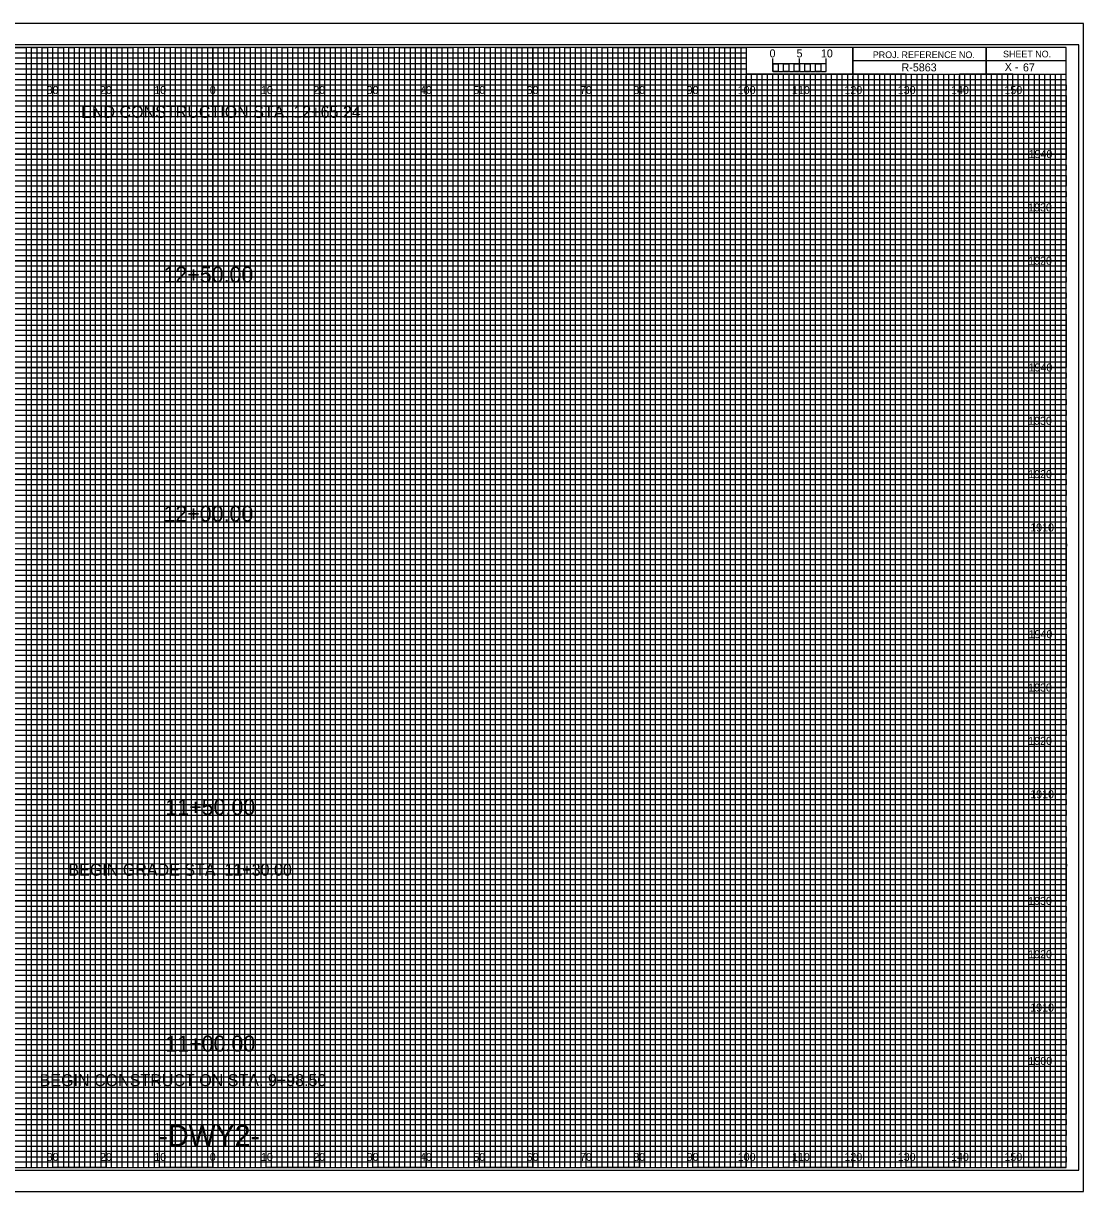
# Model space of a CAD drawing. Extents: x -13 to 323, y -4 to 214.
# Drawn here: x 124.5 to 323.3, y -4.5 to 214.5 of the extents above; entities that cross this region are included whole.
import ezdxf

# ---------------------------------------------------------------- set-up
doc = ezdxf.new("R2010")
doc.units = 0
for name, color, linetype in [('Prop XS Alignment Label', 7, 'Continuous'), ('Prop XS Bar Scale Labels', 7, 'Continuous'), ('Prop XS Elevation Labels', 7, 'Continuous'), ('Prop XS Offset Labels', 7, 'Continuous'), ('Prop XS Project Number', 7, 'Continuous'), ('Prop XS SE Text', 7, 'Continuous'), ('Prop XS Sheet Number', 7, 'Continuous'), ('Prop XS Station Labels', 7, 'Continuous'), ('Sheet Cross Section CELL', 7, 'Continuous'), ('Sheet Cross Section Grid Major CELL', 7, 'Continuous'), ('Sheet Cross Section Grid Middle CELL', 7, 'Continuous'), ('Sheet Cross Section Grid Minor 1 CELL', 7, 'Continuous'), ('Sheet Cross Section Grid Minor 2 CELL', 7, 'Continuous'), ('Sheet Cross Section Scale CELL', 7, 'Continuous'), ('Sheet Cutting Line CELL', 7, 'Continuous'), ('Sheet DOT Grid CELL', 7, 'Continuous'), ('Sheet Plot Border Inside CELL', 7, 'Continuous'), ('Sheet Plot Border Outside CELL', 7, 'Continuous')]:
    doc.layers.add(name, color=color, linetype=linetype)

msp = doc.modelspace()

# ---------------------------------------------------------------- linework, layer by layer
at = {"layer": 'Sheet Cross Section CELL'}
for p, q in [((305, 210), (305, 205)), ((305, 205), (305, 210)), ((280, 207.5), (280, 205)), ((320, 207.49), (280, 207.49)), ((280, 205), (320, 205))]:
    msp.add_line(p, q, dxfattribs=at)
for points in [[(320, 210), (0, 210), (0, 0), (320, 0)], [(280, 210), (260, 210), (260, 205.03), (280, 205.03)], [(320, 210), (280, 210), (280, 205), (320, 205)]]:
    msp.add_lwpolyline(points, close=True, dxfattribs=at)
at = {"layer": 'Sheet Cross Section Grid Major CELL'}
for p, q in [((130, 210), (120, 210)), ((130, 0), (130, 210)), ((150, 210), (140, 210)), ((140, 210), (140, 0)), ((150, 0), (150, 210)), ((170, 210), (160, 210)), ((160, 210), (160, 0)), ((170, 0), (170, 210)), ((190, 210), (180, 210)), ((180, 210), (180, 0)), ((190, 0), (190, 210)), ((210, 210), (200, 210)), ((200, 210), (200, 0)), ((210, 0), (210, 210)), ((230, 210), (220, 210)), ((220, 210), (220, 0)), ((230, 0), (230, 210)), ((250, 210), (240, 210)), ((240, 210), (240, 0)), ((250, 0), (250, 210)), ((260, 210), (260, 0)), ((270, 0), (270, 205)), ((290, 205), (280, 205)), ((280, 205), (280, 0)), ((290, 0), (290, 205)), ((310, 205), (300, 205)), ((300, 205), (300, 0)), ((310, 0), (310, 205)), ((140, 0), (130, 0)), ((160, 0), (150, 0)), ((180, 0), (170, 0)), ((200, 0), (190, 0)), ((220, 0), (210, 0)), ((240, 0), (230, 0)), ((260, 0), (250, 0)), ((280, 0), (270, 0)), ((300, 0), (290, 0)), ((320, 0), (310, 0)), ((320, 0), (320, 0))]:
    msp.add_line(p, q, dxfattribs=at)
for points in [[(0, 200), (320, 200), (320, 190), (0, 190)], [(0, 180), (320, 180), (320, 170), (0, 170)], [(0, 160), (320, 160), (320, 150), (0, 150)], [(0, 140), (320, 140), (320, 130), (0, 130)], [(0, 120), (320, 120), (320, 110), (0, 110)], [(0, 100), (320, 100), (320, 90), (0, 90)], [(0, 80), (320, 80), (320, 70), (0, 70)], [(0, 60), (320, 60), (320, 50), (0, 50)], [(0, 40), (320, 40), (320, 30), (0, 30)], [(0, 20), (320, 20), (320, 10), (0, 10)]]:
    msp.add_lwpolyline(points, dxfattribs=at)
at = {"layer": 'Sheet Cross Section Grid Middle CELL'}
for points in [[(115, 210), (125, 210), (125, 0), (135, 0), (135, 210), (145, 210), (145, 0), (155, 0), (155, 210), (165, 210), (165, 0), (175, 0), (175, 210), (185, 210), (185, 0), (195, 0), (195, 210), (205, 210), (205, 0), (215, 0), (215, 210), (225, 210), (225, 0), (235, 0), (235, 210), (245, 210), (245, 0), (255, 0), (255, 210), (259.93, 210), (260, 210), (260, 205), (264.99, 205), (264.99, 0), (275, 0), (275, 205), (285, 205), (285, 0), (295, 0), (295, 205), (305, 205), (305, 0), (315, 0), (315, 205)], [(0, 205), (275, 205)], [(0, 185), (320, 185), (320, 195), (0, 195)], [(0, 165), (320, 165), (320, 175), (0, 175)], [(0, 145), (320, 145), (320, 155), (0, 155)], [(0, 125), (320, 125), (320, 135), (0, 135)], [(0, 105), (320, 105), (320, 115), (0, 115)], [(0, 85), (320, 85), (320, 95), (0, 95)], [(0, 65), (320, 65), (320, 75), (0, 75)], [(0, 45), (320, 45), (320, 55), (0, 55)], [(0, 25), (320, 25), (320, 35), (0, 35)], [(0, 5), (320, 5), (320, 15), (0, 15)]]:
    msp.add_lwpolyline(points, dxfattribs=at)
at = {"layer": 'Sheet Cross Section Grid Minor 1 CELL'}
for p, q in [((0, 209), (260, 209)), ((260, 209), (260, 207.98)), ((260, 207.98), (0, 207.98)), ((0, 207), (260, 207)), ((260, 205.89), (0, 205.89)), ((260, 207), (260, 205.89)), ((0, 204), (320, 204))]:
    msp.add_line(p, q, dxfattribs=at)
for points in [[(0, 203), (270, 203), (320, 203), (320, 202), (0, 202)], [(0, 201), (320, 201), (320, 199), (0, 199)], [(0, 198), (320, 198), (320, 197), (0, 196.98)], [(0, 196), (320, 196), (320, 194), (0, 194)], [(0, 193), (320, 193), (320, 192), (0, 192)], [(0, 191), (320, 191), (320, 189), (0, 189)], [(0, 188), (320, 188), (320, 187), (0, 187)], [(0, 186), (320, 186), (320, 184), (0, 184)], [(0, 183), (320, 183), (320, 182), (0, 182)], [(0, 181), (320, 181), (320, 179), (0, 179)], [(0, 178), (320, 178), (320, 177), (0, 177)], [(0, 176), (320, 176), (320, 173.95), (320, 173), (320, 172), (0, 172)], [(0, 174), (320, 174), (320, 173), (0, 173)], [(0, 171), (320, 171), (320, 169), (0, 169.03)], [(0, 169.03), (320, 169), (320, 168), (0, 168)], [(0, 167), (320, 167), (320, 166), (0, 166)], [(0, 164), (320, 164), (320, 163), (0, 163)], [(0, 162), (320, 162), (320, 161), (0, 161)], [(-0.07, 158.89), (320, 158.89), (320, 157.88), (-0.07, 157.88)], [(0, 157), (320, 157), (320, 156), (0, 156)], [(0, 154), (320, 154), (320, 153), (0, 153)], [(0, 152), (320, 152), (320, 151), (0, 151)], [(0, 149), (320, 149), (320, 148), (0, 148)], [(0, 147), (320, 147), (320, 146), (0, 146)], [(0, 144), (320, 144), (320, 143), (0, 143)], [(0, 142), (320, 142), (320, 141), (0, 141)], [(0, 139), (320, 139), (319.99, 137.98), (0, 138)], [(0, 137), (320, 137), (320, 136), (0, 136)], [(0, 134), (320, 134), (320, 133), (0, 133)], [(0, 132), (320, 132), (320, 131), (0, 131)], [(0, 129), (320, 129), (320, 128), (0, 128)], [(0, 127), (320, 127), (320, 126), (0, 126)], [(0, 124), (320, 124), (320, 123), (0, 123)], [(0, 122), (320, 122), (320, 121), (0, 121)], [(0, 119), (320, 119), (320, 118), (0, 118)], [(0, 116.99), (320.07, 116.91), (320, 116), (0, 116)], [(0, 114), (320, 114), (320, 113), (0, 113)], [(0, 112), (320, 112), (320, 111), (0, 111)], [(0, 109), (320, 109), (320, 108), (0, 108)], [(0, 107), (320, 107), (320, 106), (0, 106)], [(0, 104), (320, 104), (320, 103), (0, 103)], [(0, 102), (320, 102), (320, 101), (0, 101)], [(0, 99), (320, 99), (320, 98), (0, 98)], [(0, 97), (320, 97), (320, 96), (0, 96)], [(0, 94), (320, 94), (320, 93), (0, 93)], [(0, 92), (320, 92), (320, 91), (0, 91)], [(0, 89), (320, 89), (320, 88), (0, 88)], [(0, 87), (320, 87), (320, 86), (0, 86)], [(0, 84), (320, 84), (320, 83), (0, 83)], [(0, 82), (320, 82), (320, 81), (0, 81)], [(0, 79), (320, 79), (319.99, 77.98), (0, 78)], [(0, 77), (320, 77), (320, 76), (0, 76)], [(0, 74), (320, 74), (320, 73), (0, 73)], [(0, 72), (320, 72), (320, 71), (0, 71)], [(0, 69), (320, 69), (320, 68), (0, 68)], [(0, 67), (320, 67), (320, 66), (0, 66)], [(0, 64), (320, 64), (320, 63), (0, 63)], [(0, 62), (320, 62), (320, 61), (0, 61)], [(0, 59), (320, 59), (320, 58), (0, 58)], [(0, 56.99), (320.07, 56.91), (320, 56), (0, 56)], [(0, 54), (320, 54), (320, 53), (0, 53)], [(0, 52), (320, 52), (320, 51), (0, 51)], [(0, 49), (320, 49), (320, 48), (0, 48)], [(0, 47), (320, 47), (320, 46), (0, 46)], [(0, 44), (320, 44), (320, 43), (0, 43)], [(0, 42), (320, 42), (320, 41), (0, 41)], [(0, 39), (320, 39), (320, 38), (0, 38)], [(0, 37), (320, 37), (320, 36), (0, 36)], [(0, 34), (320, 34), (320, 33), (0, 33)], [(0, 32), (320, 32), (320, 31), (0, 31)], [(0, 29), (320, 29), (320, 28), (0, 28)], [(0, 27), (320, 27), (320, 26), (0, 26)], [(0, 24), (320, 24), (320, 23), (0, 23)], [(0, 22), (320, 22), (320, 21), (0, 21)], [(0, 19), (320, 19), (320, 18), (0, 18)], [(0, 17), (320, 17), (320, 16), (0, 16)], [(0, 14), (320, 14), (320, 13), (0, 13)], [(0, 12), (320, 12), (320, 11), (0, 11)], [(0, 9), (320, 9), (320, 8), (0, 8)], [(0, 7), (320, 7), (320, 6), (0, 6)], [(0, 4), (320, 4), (320, 3), (0, 3)], [(0, 2), (320, 2), (320, 1), (0, 1)]]:
    msp.add_lwpolyline(points, dxfattribs=at)
at = {"layer": 'Sheet Cross Section Grid Minor 2 CELL'}
for p, q in [((267, 205), (266.01, 205)), ((266.01, 205), (266.01, 0)), ((267, 0), (267, 205)), ((269, 205), (268, 205)), ((268, 205), (268, 0)), ((269, 0), (269, 205)), ((266.01, 0), (265, 0)), ((268, 0), (267, 0))]:
    msp.add_line(p, q, dxfattribs=at)
for points in [[(125, 0), (126, 0), (126, 210), (127, 210), (127, 0)], [(127, 0), (128, 0), (128, 210), (129, 210), (129, 0)], [(130, 0), (131, 0), (131, 210), (132, 210), (132, 0)], [(132, 0), (133, 0), (133, 210), (134, 210), (134, 0)], [(135, 0), (136, 0), (136, 210), (137, 210), (137, 0)], [(137, 0), (138, 0), (138, 210), (139, 210), (139, 0)], [(140, 0), (141, 0), (141, 210), (142, 210), (142, 0)], [(142, 0), (143, 0), (143, 210), (144, 210), (144, 0)], [(145, 0), (146, 0), (146, 210), (147, 210), (147, 0)], [(147, 0), (148, 0), (148, 210), (149, 210), (149, 0)], [(150, 0), (151, 0), (151, 210), (152, 210), (152, 0)], [(152, 0), (153, 0), (153, 210), (154, 210), (154, 0)], [(155, 0), (156, 0), (156, 210), (157, 210), (157, 0)], [(157, 0), (158, 0), (158, 210), (159, 210), (159, 0)], [(160, 0), (161, 0), (161, 210), (162, 210), (162, 0)], [(162, 0), (163, 0), (163, 210), (164, 210), (164, 0)], [(165, 0), (166, 0), (166, 210), (167, 210), (167, 0)], [(167, 0), (168, 0), (168, 210), (169, 210), (169, 0)], [(170, 0), (171, 0), (171, 210), (172, 210), (172, 0)], [(172, 0), (173, 0), (173, 210), (174, 210), (174, 0)], [(175, 0), (176, 0), (176, 210), (177, 210), (177, 0)], [(177, 0), (178, 0), (178, 210), (179, 210), (179, 0)], [(180, 0), (181, 0), (181, 210), (182, 210), (182, 0)], [(182, 0), (183, 0), (183, 210), (184, 210), (184, 0)], [(185, 0), (186, 0), (186, 210), (187, 210), (187, 0)], [(187, 0), (188, 0), (188, 210), (189, 210), (189, 0)], [(190, 0), (191, 0), (191, 210), (192, 210), (192, 0)], [(192, 0), (193, 0), (193, 210), (194, 210), (194, 0)], [(195, 0), (196, 0), (196, 210), (197, 210), (197, 0)], [(197, 0), (198, 0), (198, 210), (199, 210), (199, 0)], [(200, 0), (201, 0), (201, 210), (202, 210), (202, 0)], [(202, 0), (203, 0), (203, 210), (204, 210), (204, 0)], [(205, 0), (206, 0), (206, 210), (207, 210), (207, 0)], [(207, 0), (208, 0), (208, 210), (209, 210), (209, 0)], [(210, 0), (211, 0), (211, 210), (212, 210), (212, 0)], [(212, 0), (213, 0), (213, 210), (214, 210), (214, 0)], [(215, 0), (216, 0), (216, 210), (217, 210), (217, 0)], [(217, 0), (218, 0), (218, 210), (219, 210), (219, 0)], [(220, 0), (221, 0), (221, 210), (222, 210), (222, 0)], [(222, 0), (223, 0), (223, 210), (224, 210), (224, 0)], [(225, 0), (226, 0), (226, 210), (227, 210), (227, 0)], [(227, 0), (228, 0), (228, 210), (229, 210), (229, 0)], [(230, 0), (231, 0), (231, 210), (232, 210), (232, 0)], [(232, 0), (233, 0), (233, 210), (234, 210), (234, 0)], [(235, 0), (236, 0), (236, 210), (237, 210), (237, 0)], [(237, 0), (238, 0), (238, 210), (239, 210), (239, 0)], [(240, 0), (241, 0), (241, 210), (242, 210), (242, 0)], [(242, 0), (243, 0), (243, 210), (244, 210), (244, 0)], [(245, 0), (246, 0), (246, 210), (247, 210), (247, 0)], [(247, 0), (248, 0), (248, 210), (249, 210), (249, 0)], [(250, 0), (251, 0), (251, 210), (252, 210), (252, 0)], [(252, 0), (253, 0), (253, 210), (254, 210), (254, 0)], [(255, 0), (256, 0), (256, 210), (257, 210), (257, 0)], [(257, 0), (258, 0), (258, 210), (259, 210), (259, 0)], [(260, 0), (261, 0), (261, 205), (262.02, 205), (262.02, 0)], [(262, 0), (263, 0), (263, 205), (263.99, 205), (263.99, 0)], [(270, 0), (270.98, 0), (270.98, 205), (272, 205), (272, 0)], [(272, 0), (273, 0), (273, 205), (274.05, 205), (274.05, 0)], [(275, 0), (276, 0), (276, 205), (277, 205), (277, 0)], [(277, 0), (278, 0), (278, 205), (279, 205), (279, 0)], [(280, 0), (281, 0), (281, 205), (282, 205), (282, 0)], [(282, 0), (283, 0), (283, 205), (284, 205), (284, 0)], [(285, 0), (286, 0), (286, 205), (287, 205), (287, 0)], [(287, 0), (288, 0), (288, 205), (289, 205), (289, 0)], [(290, 0), (291, 0), (291, 205), (292, 205), (292, 0)], [(292, 0), (293, 0), (293, 205), (294, 205), (294, 0)], [(295, 0), (296, 0), (296, 205), (297, 205), (297, 0)], [(297, 0), (298, 0), (298, 205), (299, 205), (299, 0)], [(300, 0), (301, 0), (301, 205), (302, 205), (302, 0)], [(302, 0), (303, 0), (303, 205), (304, 205), (304, 0)], [(305, 0), (306, 0), (306, 205), (307, 205), (307, 0)], [(307, 0), (308, 0), (308, 205), (309, 205), (309, 0)], [(310, 0), (311, 0), (311, 205), (312, 205), (312, 0)], [(312, 0), (313, 0), (313, 205), (314, 205), (314, 0)], [(315, 0), (316, 0), (316, 205), (317, 205), (317, 0)], [(317, 0), (318, 0), (318, 205), (319, 205), (319, 0)]]:
    msp.add_lwpolyline(points, dxfattribs=at)
at = {"layer": 'Sheet Cross Section Scale CELL'}
for p, q in [((265, 205.49), (265, 207.9)), ((265, 206.9), (265, 207.9)), ((270, 205.49), (270, 207.9)), ((275, 205.49), (275, 207.9)), ((275, 206.9), (275, 207.9))]:
    msp.add_line(p, q, dxfattribs=at)
for points in [[(275, 206.9), (265, 206.9), (265, 205.49), (275, 205.49)], [(265, 206.9), (266, 206.9), (266, 205.49), (265, 205.49)], [(267, 206.9), (268, 206.9), (268, 205.49), (267, 205.49)], [(269, 206.9), (270, 206.9), (270, 205.49), (269, 205.49)], [(271, 206.9), (272, 206.9), (272, 205.49), (271, 205.49)], [(273, 206.9), (274, 206.9), (274, 205.49), (273, 205.49)]]:
    msp.add_lwpolyline(points, close=True, dxfattribs=at)
at = {"layer": 'Sheet Cutting Line CELL'}
for p, q in [((323.3, 214.5), (-13.4, 214.5)), ((-13.4, -4.5), (323.3, -4.5))]:
    msp.add_line(p, q, dxfattribs=at)
at = {"layer": 'Sheet DOT Grid CELL'}
for p, q in [((130, 0), (130, 210)), ((140, 0), (140, 210)), ((150, 0), (150, 210)), ((160, 0), (160, 210)), ((170, 0), (170, 210)), ((180, 0), (180, 210)), ((190, 0), (190, 210)), ((200, 0), (200, 210)), ((210, 0), (210, 210)), ((220, 0), (220, 210)), ((230, 0), (230, 210)), ((240, 0), (240, 210)), ((250, 0), (250, 210)), ((260, 0), (260, 204.69)), ((270, 0), (270, 204.69)), ((280, 0), (280, 204.69)), ((290, 0), (290, 204.69)), ((300, 0), (300, 204.69)), ((310, 0), (310, 204.69)), ((0, 200), (320, 200)), ((0, 190), (320, 190)), ((0, 180), (320, 180)), ((0, 170), (320, 170)), ((0, 160), (320, 160)), ((0, 150), (320, 150)), ((0, 140), (320, 140)), ((0, 130), (320, 130)), ((0, 120), (320, 120)), ((0, 110), (320, 110)), ((0, 100), (320, 100)), ((0, 90), (320, 90)), ((0, 80), (320, 80)), ((0, 70), (320, 70)), ((0, 60), (320, 60)), ((0, 50), (320, 50)), ((0, 40), (320, 40)), ((0, 30), (320, 30)), ((0, 20), (320, 20)), ((0, 10), (320, 10))]:
    msp.add_line(p, q, dxfattribs=at)
at = {"layer": 'Sheet Plot Border Inside CELL'}
msp.add_lwpolyline([(-10.8, -0.5), (322.4, -0.5), (322.4, 210.5), (-10.8, 210.5)], close=True, dxfattribs=at)
at = {"layer": 'Sheet Plot Border Outside CELL'}
msp.add_lwpolyline([(-13.4, -4.5), (323.3, -4.5), (323.3, 214.5), (-13.4, 214.5)], close=True, dxfattribs=at)

# ---------------------------------------------------------------- texts
at = {"layer": 'Prop XS Alignment Label'}
msp.add_text('-DWY2-', height=4, dxfattribs=at).set_placement((149.85, 4))
at = {"layer": 'Prop XS Bar Scale Labels'}
for s, p in [('5', (269.47, 208.12)), ('10', (274.04, 208.12))]:
    msp.add_text(s, height=1.5, dxfattribs=at).set_placement(p)
at = {"layer": 'Prop XS Elevation Labels'}
for s, p in [('1940', (312.97, 189.25)), ('1930', (312.89, 179.25)), ('1920', (312.9, 169.25)), ('1940', (312.97, 149.25)), ('1930', (312.89, 139.25)), ('1920', (312.9, 129.25)), ('1910', (313.28, 119.25)), ('1940', (312.97, 99.25)), ('1930', (312.89, 89.25)), ('1920', (312.9, 79.25)), ('1910', (313.28, 69.25)), ('1930', (312.89, 49.25)), ('1920', (312.9, 39.25)), ('1910', (313.28, 29.25)), ('1900', (312.95, 19.25))]:
    msp.add_text(s, height=1.5, dxfattribs=at).set_placement(p)
at = {"layer": 'Prop XS Offset Labels'}
for s, p in [('30', (128.86, 201.25)), ('20', (138.86, 201.25)), ('10', (149.04, 201.25)), ('0', (159.45, 201.25)), ('0', (159.45, 201.25)), ('10', (169.04, 201.25)), ('20', (178.86, 201.25)), ('30', (188.86, 201.25)), ('40', (198.86, 201.25)), ('50', (208.86, 201.25)), ('60', (218.86, 201.25)), ('70', (228.86, 201.25)), ('80', (238.86, 201.25)), ('90', (248.86, 201.25)), ('100', (258.44, 201.25)), ('110', (268.62, 201.25)), ('120', (278.44, 201.25)), ('130', (288.44, 201.25)), ('140', (298.44, 201.25)), ('150', (308.44, 201.25)), ('30', (128.86, 1.25)), ('20', (138.86, 1.25)), ('10', (149.04, 1.25)), ('0', (159.45, 1.25)), ('0', (159.45, 1.25)), ('10', (169.04, 1.25)), ('20', (178.86, 1.25)), ('30', (188.86, 1.25)), ('40', (198.86, 1.25)), ('50', (208.86, 1.25)), ('60', (218.86, 1.25)), ('70', (228.86, 1.25)), ('80', (238.86, 1.25)), ('90', (248.86, 1.25)), ('100', (258.44, 1.25)), ('110', (268.62, 1.25)), ('120', (278.44, 1.25)), ('130', (288.44, 1.25)), ('140', (298.44, 1.25)), ('150', (308.44, 1.25))]:
    msp.add_text(s, height=1.5, dxfattribs=at).set_placement(p)
at = {"layer": 'Prop XS Project Number'}
msp.add_text('R-5863', height=1.5, dxfattribs=at).set_placement((289.16, 205.5))
at = {"layer": 'Prop XS SE Text'}
for s, p in [('END CONSTRUCTION STA. 12+65.24', (135.34, 196.79)), ('BEGIN GRADE STA. 11+30.00', (132.95, 54.72)), ('BEGIN CONSTRUCTION STA. 9+98.50', (127.56, 15.27))]:
    msp.add_text(s, height=2.25, rotation=0.0068, dxfattribs=at).set_placement(p)
at = {"layer": 'Prop XS Sheet Number'}
msp.add_text('67', height=1.5, dxfattribs=at).set_placement((311.92, 205.5))
at = {"layer": 'Prop XS Station Labels'}
for s, p in [('12+50.00', (150.77, 165.9)), ('12+00.00', (150.77, 121.09)), ('11+50.00', (151.13, 66.1)), ('11+00.00', (151.13, 21.75))]:
    msp.add_text(s, height=3, dxfattribs=at).set_placement(p)
at = {"layer": 'Sheet Cross Section CELL'}
for s, height, p in [('PROJ. REFERENCE NO.', 1.25, (283.77, 207.99)), ('SHEET NO.', 1.25, (308.19, 208.12)), ('X -    ', 1.5, (308.5, 205.58))]:
    msp.add_text(s, height=height, dxfattribs=at).set_placement(p)
at = {"layer": 'Sheet Cross Section Scale CELL'}
msp.add_text('0', height=1.5, dxfattribs=at).set_placement((264.41, 208.12))

doc.saveas('drawing.dxf')
